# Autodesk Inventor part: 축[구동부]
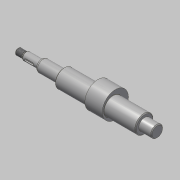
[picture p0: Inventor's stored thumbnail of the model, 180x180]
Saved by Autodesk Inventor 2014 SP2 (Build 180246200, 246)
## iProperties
Created: 2015-12
Part Number: 축[구동부]
Document SubType Name: Modeling
Designer: mdu
Density: 7.86 g/cm^3
Material: 강철, 연강
Appearance: 강철
Mass: 484.678 g
Surface Area: 125.968 cm^2
Volume: 61.6639 cm^3
Author: mdu
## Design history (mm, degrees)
sketch "스케치1"
  geometry: L1 (62, 100.9)-(62, 67.1) reference; L2 (51, 101.2)-(51, 84) reference; L3 (-51, 84)-(-51, 101.2) reference; L4 (-62, 67.1)-(-62, 100.9) reference; L5 (-51.6, 91.5)-(-61.4, 91.5) reference; L6 (51.6, 91.5)-(61.4, 91.5) reference; L7 (67, 84)-(-109, 84); L8 (-77, 64.201)-(-77, 103.799) reference; L9 (67, 84)-(67, 91.5); L10 (67, 91.5)-(51, 91.5); L11 (51, 91.5)-(51, 95.5); L12 (51, 95.5)-(-51, 95.5); L13 (-51, 95.5)-(-51, 91.5); L14 (-51, 91.5)-(-79, 91.5); L15 (-79, 91.5)-(-79, 89); L16 (-79, 89)-(-99, 89); L17 (-99, 89)-(-99, 87); L18 (-100.5, 88)-(-109, 88); L19 (-109, 88)-(-109, 84); L20 (-99, 87)-(-100.5, 87); L21 (-100.5, 87)-(-100.5, 88); 2 further points
  constraints: 32 end point, 7 parallel, 6 point on line, 5 perpendicular, 2 collinear, 2 horizontal, 1 midpoint, 4 other
  dimensions: "d0" = 5 distance from line of L7.start L1; "d2" = 2 distance between parallel lines of L15 L8; "d3" = 23 diameter of L12 L7; "d4" = 10 diameter of L16 L7; "d5" = 1.5 distance of L17.end L20.end; "d6" = 6 diameter of L20 L7; "d7" = 20 distance of L15.end L16.end; "d8" = 10 distance between parallel lines of L17 L19; "d9" = 8 diameter of L18 L7
revolve "회전1" sketch "스케치1" stored, may be unused: angle "d10" = 90 deg
sketch "스케치2"
  geometry: C1 r 11.5 at (84, 0) reference; C2 r 11.5 at (84, 0) reference; C3 r 16.5 at (87, 0); 1 further point
  constraints: 1 centre point, 1 horizontal alignment
  dimensions: "d11" = 33 diameter of C3; "d12" = 3 distance of C3.centre C1.centre
extrude "돌출1" join sketch "스케치2" stored distance "d13" = 22; taper "d14" = 0 deg
chamfer "모따기1" distance "d15" = 1; stored, may be unused: second distance "d16" = 2, angle "d17" = 45 deg
feature "스레드1" dims "d18" = 10, "d19" = 0
node "작업 평면1"
sketch "스케치3"
  geometry: L1 (-5.5, -1.5)-(3.5, -1.5); L2 (3.5, 1.5)-(-5.5, 1.5); L3 (-10, -4)-(-10, 4) reference; A1 r 1.5 centre (3.5, 0) between (3.5, -1.5) and (3.5, 1.5); A2 r 1.5 centre (-5.5, 0) between (-5.5, 1.5) and (-5.5, -1.5); 2 further points
  constraints: 4 end point, 4 point on circle, 4 tangent, 2 centre point, 1 horizontal, 1 horizontal alignment, 1 midpoint, 1 parallel
  dimensions: "d20" = 3 distance between parallel lines of L1 L2; "d21" = 12 dimension on A1 A2; "d22" = 3 distance edge to line of A2 L3
extrude "돌출2" cut sketch "스케치3" distance "d23" = 1.8; taper "d24" = 0 deg
fillet "모깎기1" dims "d25" = 0.3
fillet "모깎기2" dims "d26" = 3
node "솔리드1"
node "참조1"
node "참조2"
node "참조3"
node "참조4"
node "참조5"
node "투영된 루프1"
